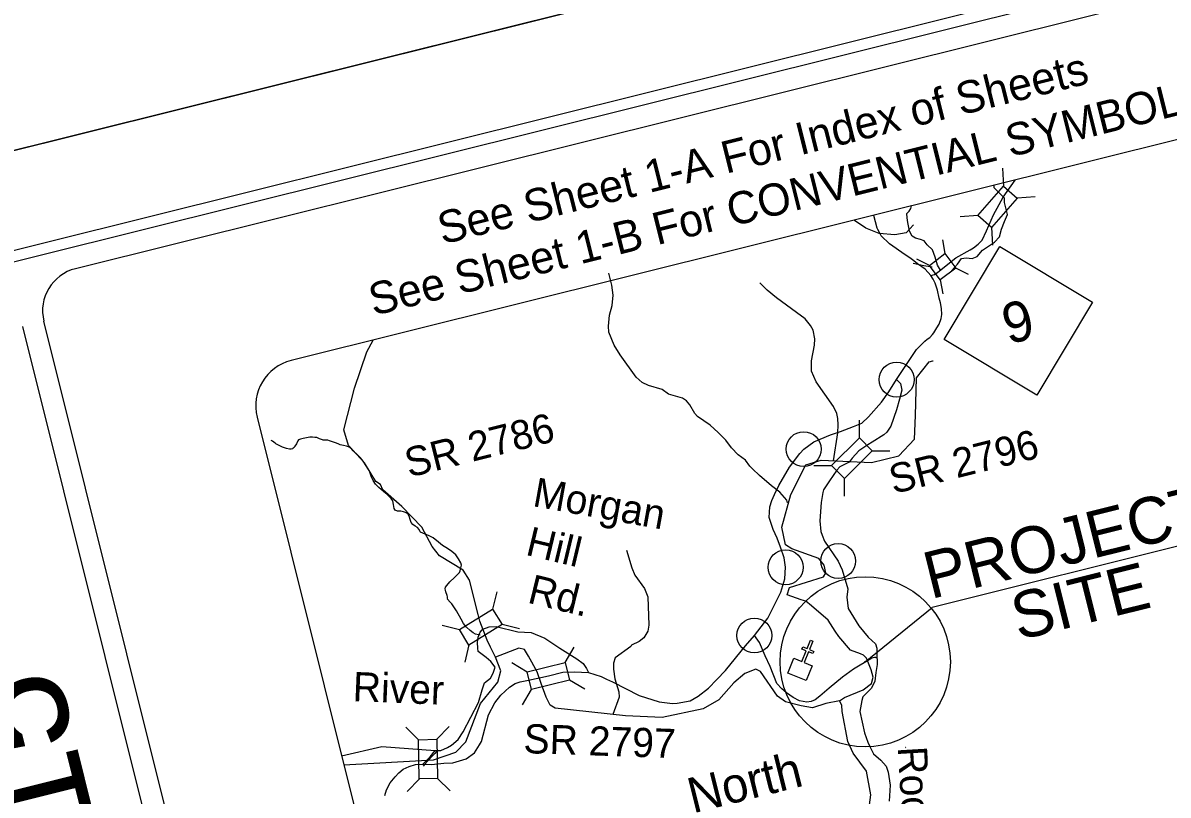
# Model space of a CAD drawing. Extents: x 1030323 to 1034123, y 654802 to 657751.
# Drawn here: x 1030543.2 to 1030807.6, y 656841.8 to 657020.2 of the extents above; entities that cross this region are included whole.
import ezdxf

# ---------------------------------------------------------------- set-up
doc = ezdxf.new("R2010")
doc.units = 0
for name, color, linetype in [('COGO Default Parcel', 7, 'Continuous'), ('Default', 7, 'Continuous'), ('Old_Level_1', 7, 'Continuous'), ('Prop Dimension', 7, 'Continuous'), ('Prop Dimension Text', 7, 'Continuous'), ('Prop Horizontal Alignment', 7, 'Continuous'), ('Prop Horizontal Alignment Tick Large', 7, 'Continuous'), ('Prop RDY Alternate Text Blue', 7, 'Continuous'), ('Prop Shade Light', 7, 'Continuous'), ('Prop Shade Medium', 7, 'Continuous'), ('Sheet Cutting Line CELL', 7, 'Continuous'), ('Sheet Plot Border Inside CELL', 7, 'Continuous'), ('Sheet Plot Border Outside CELL', 7, 'Continuous'), ('Sheet Title CELL', 7, 'Continuous')]:
    doc.layers.add(name, color=color, linetype=linetype)

msp = doc.modelspace()

# ---------------------------------------------------------------- linework, layer by layer
at = {"layer": 'COGO Default Parcel'}
for points in [[(1030757.59, 656962.93), (1030758.96, 656964.51), (1030759.89, 656965.76), (1030760.97, 656965.96), (1030762.35, 656965.82), (1030763.5, 656966.28), (1030764.76, 656967.71), (1030767.57, 656969.56), (1030768.71, 656970.77), (1030769.18, 656972.59), (1030769.87, 656974.36), (1030770.57, 656975.92), (1030769.87, 656978.74), (1030769.83, 656979.75), (1030767.45, 656982.14), (1030767.43, 656982.67)], [(1030740.61, 656972.5), (1030740.45, 656972.82), (1030739.66, 656975.74)], [(1030755.09, 656963.07), (1030754.36, 656964.22), (1030753.84, 656966.08), (1030753.21, 656967.75), (1030752.02, 656968.91), (1030751.32, 656969.9), (1030750.47, 656970.14), (1030749.29, 656970.51), (1030748.54, 656970.96), (1030747.93, 656972.11), (1030747.73, 656972.93), (1030747.54, 656974.1), (1030747.37, 656975.2), (1030747.27, 656976.15), (1030747.8, 656976.68), (1030748.24, 656977.35), (1030748.38, 656977.92)], [(1030748.82, 656973.55), (1030747.18, 656971.69), (1030744.55, 656971.25), (1030740.9, 656971.56), (1030737.85, 656972.8), (1030735.45, 656974.44), (1030735.07, 656974.6)], [(1030752.84, 656961.88), (1030751.5, 656963.33), (1030749.76, 656964.55), (1030748.91, 656965.24), (1030747.97, 656965.92), (1030746.94, 656966.65), (1030743.29, 656969.16), (1030741.38, 656971.05), (1030740.96, 656971.81), (1030740.61, 656972.5)], [(1030719.77, 656909.34), (1030719.6, 656909.97), (1030718.01, 656911.83), (1030716.02, 656913.3), (1030713.28, 656915.69), (1030711.63, 656917.16), (1030711.04, 656917.81), (1030710.08, 656919.17), (1030708.35, 656920.47), (1030706.81, 656922.08), (1030705.54, 656923.82), (1030703.75, 656925.59), (1030701.9, 656927.28), (1030698.93, 656929.32), (1030698.38, 656929.99), (1030697.17, 656932), (1030696.46, 656932.89), (1030695.47, 656933.49), (1030692.25, 656934.44), (1030690.8, 656935.51), (1030687.65, 656936.47), (1030686.16, 656937.16), (1030684.82, 656938.4), (1030681.08, 656943.51), (1030679.71, 656945.75), (1030678.47, 656948.76), (1030678.4, 656950.12), (1030678.63, 656952.7), (1030679.23, 656954.91), (1030679.51, 656957.28), (1030679.19, 656959.63), (1030678.53, 656962.36)], [(1030730.35, 656919.08), (1030731.39, 656925.48), (1030731.44, 656927.35), (1030731.34, 656928.86), (1030731.1, 656929.96), (1030730.38, 656931.59), (1030726.4, 656937.29), (1030725.32, 656939.74), (1030725.25, 656942.14), (1030725.99, 656945.8), (1030726.03, 656947.19), (1030725.68, 656949.19), (1030725.07, 656950.29), (1030723.81, 656951.85), (1030721.85, 656953.33), (1030717.22, 656956.69), (1030715.06, 656958.46), (1030713.35, 656960.17)], [(1030744.94, 656937.8), (1030749.56, 656944.78), (1030751.49, 656946.65), (1030752.03, 656947.18), (1030752.64, 656947.52), (1030753.23, 656948.19), (1030753.53, 656948.64), (1030754.26, 656949.73), (1030754.76, 656950.58), (1030755.24, 656951.94), (1030755.37, 656952.84), (1030755.29, 656954.27), (1030755.04, 656955.53), (1030754.79, 656956.63), (1030754.34, 656958.45), (1030753.85, 656960.12), (1030753.38, 656961), (1030752.84, 656961.88)], [(1030652.3, 656873.67), (1030651.19, 656876.02), (1030650.44, 656877.61), (1030648.69, 656881.99), (1030648.32, 656883.54), (1030646.31, 656891.47), (1030644.87, 656893.83), (1030639.37, 656897.11), (1030637.67, 656899.23), (1030635.31, 656903.71), (1030630.72, 656908.48), (1030626.34, 656912.32), (1030625.75, 656913.6), (1030624.68, 656914.27), (1030622.05, 656918.57), (1030618.4, 656922.57), (1030617.32, 656926.18), (1030619.74, 656935.86), (1030622.6, 656944.23), (1030624.09, 656946.93)], [(1030723.94, 656886.61), (1030722.92, 656886.92), (1030719.67, 656888.08), (1030720.23, 656889.82), (1030728.02, 656892.23), (1030728.6, 656893.16), (1030728.22, 656894.91), (1030726.95, 656896.52), (1030720.74, 656898.71), (1030719.3, 656899.67), (1030718.43, 656903.7), (1030720.53, 656911.28), (1030723.96, 656918.14), (1030727.54, 656919.22), (1030739.15, 656918.63), (1030745.42, 656920.2), (1030749.07, 656924.02), (1030749.29, 656929.53), (1030749.5, 656938.22), (1030752.42, 656941.95), (1030753.31, 656942.15)], [(1030753.31, 656942.15), (1030753.39, 656942.18)], [(1030712.1, 656878.7), (1030715.17, 656882.68), (1030718.19, 656888.73), (1030719.13, 656891.77), (1030719.31, 656894.46), (1030718.99, 656896.62), (1030718.15, 656899.12), (1030717.35, 656901.21), (1030716.46, 656903.2), (1030715.52, 656905.96), (1030715.68, 656908.41), (1030716.11, 656909.91), (1030716.75, 656911.3), (1030717.71, 656913.36), (1030720.18, 656917.56), (1030722.61, 656920.77), (1030723.48, 656921.75), (1030725.86, 656923.42), (1030729.66, 656925.08), (1030732, 656925.85), (1030734.99, 656926.96), (1030736.94, 656927.78), (1030738.43, 656929.18), (1030741.47, 656932.58), (1030743.15, 656934.97), (1030744.94, 656937.8)], [(1030744.94, 656937.8), (1030745.87, 656936.89), (1030746.11, 656935.4), (1030745.58, 656933.29), (1030744.89, 656930.81), (1030743.57, 656927.09), (1030742.71, 656925.69), (1030742, 656925.02), (1030739.33, 656923.32), (1030738.33, 656922.75), (1030736.2, 656921.34), (1030734.68, 656919.66)], [(1030734.68, 656919.66), (1030733.95, 656918.76), (1030731.86, 656917.66), (1030731.14, 656916.87), (1030729.46, 656914.42), (1030728.09, 656912.38), (1030727.87, 656911.74), (1030727.52, 656909.39), (1030727.19, 656905.19), (1030727.47, 656902.71), (1030727.78, 656901.84), (1030728.27, 656900.49), (1030731.44, 656895.9), (1030732.36, 656893.89), (1030733.71, 656889.46), (1030733.44, 656887.58), (1030733.73, 656884.92), (1030736.19, 656880.9), (1030738.36, 656878.29), (1030740.09, 656876.76), (1030740.38, 656875.78), (1030740.37, 656874.73)], [(1030682.55, 656898.42), (1030683.81, 656894.3), (1030684.49, 656892.66), (1030686.76, 656889.54), (1030687.51, 656887.61), (1030687.76, 656881.08), (1030687.52, 656879.73), (1030686.55, 656878.18), (1030685.51, 656877.32), (1030683.75, 656876.5), (1030683.6, 656876.17), (1030679.98, 656873.57), (1030679.59, 656872.29), (1030679.55, 656870.91), (1030679.91, 656868.72), (1030680.78, 656865.67), (1030680.85, 656864.49), (1030679.44, 656860.45)], [(1030731.57, 656878.5), (1030730.77, 656879.71), (1030729.12, 656882.21), (1030725.29, 656885.53), (1030723.94, 656886.61)], [(1030673.82, 656870.18), (1030676.71, 656869.21), (1030677.93, 656868.65), (1030679.33, 656867.98), (1030685.48, 656864.84), (1030690.09, 656863.36), (1030693.2, 656863.03), (1030694.27, 656863.08), (1030697.26, 656863.63), (1030699.13, 656864.66), (1030701.49, 656866.57), (1030703.46, 656868.54), (1030705.44, 656870.6), (1030710.05, 656876.34), (1030712.1, 656878.7)], [(1030731.76, 656863.61), (1030732.92, 656864.35), (1030737.18, 656866.15), (1030739.15, 656867.63), (1030739.53, 656869.06), (1030739.08, 656870.77), (1030738, 656873.43), (1030737.31, 656874.18), (1030736.58, 656874.43), (1030734.26, 656875.3), (1030731.57, 656878.5)], [(1030731.76, 656863.61), (1030728.56, 656862.97), (1030725.53, 656862.03), (1030722.92, 656862.47), (1030719.32, 656863.36), (1030717.47, 656864.72), (1030713.48, 656870.36), (1030712.43, 656870.92), (1030709.86, 656869.9), (1030707.36, 656867.8), (1030703.87, 656863.82), (1030700.28, 656861.78), (1030690.79, 656859.73), (1030682.33, 656860.13), (1030666.13, 656861.94), (1030664.97, 656862.63), (1030664, 656864.49), (1030662.86, 656867.61), (1030661.97, 656870.29), (1030659.98, 656873.93), (1030659.04, 656875.45), (1030657.74, 656875.77), (1030652.3, 656873.67)], [(1030617.31, 656848.84), (1030637.98, 656850.01), (1030643.19, 656851.75), (1030645.47, 656854.11), (1030648.84, 656863.02), (1030652.9, 656867.93), (1030653.59, 656870.53), (1030652.3, 656873.67)], [(1030740.37, 656874.73), (1030740.48, 656872.03), (1030740.15, 656870.12), (1030739.9, 656868.12), (1030739.12, 656866.54), (1030737.17, 656864.5), (1030736.88, 656863.68), (1030736.46, 656861.15), (1030737.55, 656856.22), (1030738.32, 656854.05), (1030738.84, 656852.92), (1030739.62, 656851.38), (1030741.32, 656849.87), (1030742.53, 656848.49), (1030742.98, 656847.12), (1030743.47, 656844.15), (1030743.19, 656840.4)], [(1030664.59, 656869.42), (1030667.88, 656870.21), (1030670.57, 656870.32), (1030673.82, 656870.18)], [(1030635.53, 656849.01), (1030637.56, 656848.91), (1030640.42, 656849.19), (1030642.45, 656849.32), (1030645.57, 656850.2), (1030647.51, 656851.57), (1030648.65, 656853.45), (1030649.12, 656854.23), (1030650.74, 656860.39), (1030652.19, 656863.18), (1030653.52, 656864.9), (1030655.58, 656866.77), (1030656.89, 656867.59), (1030658.02, 656867.99), (1030659.97, 656868.36), (1030664.59, 656869.42)], [(1030763.46, 656805.71), (1030761.88, 656806.58), (1030753.15, 656807.52), (1030746.75, 656809.86), (1030743.2, 656811.93), (1030742.76, 656816.18), (1030741.52, 656818.34), (1030739.98, 656819.77), (1030739.15, 656822.21), (1030739.79, 656827.13), (1030738.2, 656832.4), (1030738.18, 656836.13), (1030738.96, 656841.88), (1030737.95, 656847.35), (1030734.88, 656851.54), (1030733.68, 656854.21), (1030732.33, 656861.16), (1030732.26, 656862.62), (1030731.76, 656863.61)], [(1030626.78, 656841.76), (1030627.15, 656843.07), (1030628.02, 656844.66), (1030629.18, 656846.06), (1030629.98, 656846.99), (1030630.99, 656847.79), (1030632.38, 656848.43), (1030633.84, 656848.91), (1030635.53, 656849.01)]]:
    msp.add_lwpolyline(points, dxfattribs=at)
msp.add_circle((1030737.7, 656872.62), 19.65, dxfattribs=at)
at = {"layer": 'Default'}
for p, q in [((1030755.88, 656947.11), (1030768.75, 656968.53)), ((1030768.75, 656968.53), (1030790.17, 656955.66)), ((1030790.17, 656955.66), (1030777.3, 656934.24)), ((1030777.3, 656934.24), (1030755.88, 656947.11)), ((1030668.39, 656872.48), (1030670.51, 656876.01)), ((1030723.05, 656875.58), (1030723.27, 656876.1)), ((1030724.08, 656875.16), (1030723.05, 656875.58)), ((1030723.07, 656872.71), (1030724.08, 656875.16)), ((1030723.27, 656876.1), (1030724.3, 656875.67)), ((1030724.3, 656875.67), (1030725.09, 656877.61)), ((1030725.61, 656877.4), (1030724.81, 656875.46)), ((1030724.81, 656875.46), (1030725.84, 656875.04)), ((1030725.09, 656877.61), (1030725.61, 656877.4)), ((1030656.1, 656872.44), (1030659.63, 656870.32)), ((1030719.83, 656870.03), (1030721.24, 656873.46)), ((1030721.24, 656873.46), (1030723.07, 656872.71)), ((1030724.6, 656874.95), (1030723.59, 656872.5)), ((1030723.59, 656872.5), (1030725.44, 656871.73)), ((1030725.63, 656874.52), (1030724.6, 656874.95)), ((1030725.84, 656875.04), (1030725.63, 656874.52)), ((1030724.03, 656868.3), (1030719.83, 656870.03)), ((1030725.44, 656871.73), (1030724.03, 656868.3)), ((1030669.39, 656868.49), (1030672.92, 656866.37)), ((1030658.53, 656862.7), (1030660.65, 656866.23))]:
    msp.add_line(p, q, dxfattribs=at)
for points in [[(1030769.55, 656979.93), (1030772.31, 656983.88)], [(1030754.46, 656962.61), (1030758.59, 656965.93), (1030761.94, 656967.75), (1030762.71, 656968.28), (1030763.79, 656969.1), (1030764.66, 656970.05), (1030765.69, 656972.14), (1030767.32, 656975.89), (1030768.59, 656978.27), (1030769.55, 656979.93)], [(1030753.14, 656963.76), (1030751.21, 656964.09), (1030748.76, 656964.61)], [(1030752.84, 656961.88), (1030753.72, 656962.12), (1030754.46, 656962.61)], [(1030648.78, 656878.77), (1030648.42, 656878.83), (1030647.71, 656879.04), (1030647.15, 656879.33), (1030646.5, 656879.86), (1030645.62, 656880.61), (1030644.9, 656881.47), (1030644.37, 656882.51), (1030643.34, 656884.4), (1030642.21, 656885.98), (1030641.9, 656886.33), (1030641.2, 656887.19), (1030641.21, 656887.25), (1030641.26, 656887.61), (1030641.18, 656887.96), (1030640.89, 656888.75), (1030640.76, 656889.17), (1030640.71, 656889.47), (1030640.76, 656889.83), (1030641.1, 656890.23), (1030641.82, 656891.1), (1030642.84, 656892.1), (1030643.69, 656892.91), (1030643.98, 656893.27), (1030644.14, 656893.63), (1030644.29, 656894.32), (1030644.46, 656894.91), (1030644.29, 656895.47), (1030643.79, 656896.43), (1030643.14, 656897.3), (1030642.25, 656898.11), (1030641.25, 656898.8), (1030640.08, 656899.49), (1030639.17, 656900.26), (1030637.95, 656901.25), (1030637.02, 656901.76), (1030635.01, 656902.54), (1030634.99, 656902.59), (1030634.97, 656902.64), (1030634.69, 656903.17), (1030634.31, 656903.62), (1030633.8, 656903.98), (1030633.26, 656904.33), (1030632.84, 656904.78), (1030632.63, 656905.52), (1030632.41, 656906.26), (1030632.05, 656906.82), (1030631.53, 656907.15), (1030631.08, 656907.3), (1030630.44, 656907.4), (1030629.68, 656907.44), (1030629.15, 656907.67), (1030628.91, 656908.06), (1030628.8, 656908.99), (1030628.62, 656909.78), (1030628.23, 656910.38), (1030627.35, 656911.25), (1030626.47, 656911.96), (1030625.41, 656912.85), (1030624.62, 656913.62), (1030624.08, 656914.49), (1030623.72, 656915.3), (1030623.28, 656916.4), (1030623, 656917.04), (1030622.5, 656917.92), (1030621.8, 656918.97), (1030621.13, 656919.77), (1030620.33, 656920.56), (1030619.5, 656921.38), (1030619.14, 656921.72), (1030618.7, 656922.13), (1030618.55, 656922.17), (1030618.36, 656922.3), (1030617.91, 656922.4), (1030617.21, 656922.61), (1030616.5, 656922.75), (1030615.97, 656922.95), (1030615.36, 656923.22), (1030614.7, 656923.44), (1030614.01, 656923.7), (1030613.6, 656923.8), (1030613.19, 656923.85), (1030612.82, 656923.83), (1030612.52, 656923.84), (1030612.36, 656923.88), (1030611.67, 656924.16), (1030611.11, 656924.4), (1030610.65, 656924.46), (1030610.09, 656924.53), (1030609.48, 656924.49), (1030607.92, 656924.2), (1030607.32, 656924.08), (1030607.04, 656924.01), (1030606.84, 656923.91), (1030606.69, 656923.68), (1030606.36, 656923.01), (1030606.02, 656922.43), (1030605.82, 656922.15), (1030605.64, 656921.98), (1030605.45, 656921.85), (1030605.18, 656921.75), (1030604.77, 656921.73), (1030604.07, 656921.86), (1030603.13, 656922.2), (1030602.2, 656922.63), (1030601.61, 656922.96), (1030601.44, 656923.13), (1030601.15, 656923.37), (1030600.81, 656923.59), (1030600.5, 656923.74)], [(1030649.26, 656879.99), (1030649.43, 656880.18), (1030650.88, 656880.74), (1030652.51, 656880.8), (1030657.46, 656879.51), (1030660.59, 656879.4), (1030663.69, 656878.11), (1030667.21, 656875.79), (1030671.13, 656873.28), (1030672.54, 656872.21), (1030673.36, 656871.08), (1030673.82, 656870.18)], [(1030638.4, 656852.16), (1030639.7, 656852.17), (1030641.28, 656852.8), (1030642.15, 656853.4), (1030643.74, 656854.68), (1030644.88, 656856.42), (1030648.37, 656863.24), (1030649.22, 656866.14), (1030649.76, 656867.8), (1030651.14, 656868.87), (1030651.78, 656869.99), (1030652.24, 656871.37), (1030651.25, 656872.73), (1030650.19, 656873.61), (1030648.35, 656874.99), (1030648.22, 656875.8), (1030648.17, 656877.09), (1030648.33, 656878.28), (1030648.81, 656879.47), (1030649.26, 656879.99)], [(1030738.95, 656873.33), (1030735, 656870.93), (1030732.42, 656869.04), (1030729.36, 656866.56), (1030727.22, 656864.66), (1030726.13, 656863.83), (1030725.18, 656863.44), (1030724.17, 656863.3), (1030722.48, 656863.61), (1030721.06, 656864.38), (1030719.55, 656865.44), (1030718.46, 656866.4), (1030717.26, 656867.63), (1030715.77, 656871.53), (1030714.61, 656874.03), (1030713.29, 656877.05), (1030712.1, 656878.7)], [(1030616.79, 656850.92), (1030626.12, 656853.03), (1030638.4, 656852.16)], [(1030638.72, 656851.94), (1030638.32, 656851.44), (1030637.95, 656851.09), (1030636.66, 656849.71), (1030636.03, 656848.95), (1030635.65, 656848.55)], [(1030636.71, 656850.12), (1030637.27, 656850.66), (1030638.4, 656852.16)], [(1030635.53, 656849.01), (1030636.71, 656850.12)]]:
    msp.add_lwpolyline(points, dxfattribs=at)
msp.add_lwpolyline([(1030659.63, 656870.32), (1030668.39, 656872.5), (1030669.4, 656868.42), (1030660.65, 656866.23)], close=True, dxfattribs=at)
at = {"layer": 'Old_Level_1'}
for p, q in [((1030747.06, 656852.81), (1030747, 656852.8)), ((1030747.02, 656852.84), (1030747.03, 656852.78))]:
    msp.add_line(p, q, dxfattribs=at)
at = {"layer": 'Prop Dimension'}
for p in [(1030817.25, 656901.17), (1030737.7, 656872.62)]:
    msp.add_line(p, (1030753.13, 656885.18), dxfattribs=at)
at = {"layer": 'Prop Horizontal Alignment'}
msp.add_line((1030740.14, 656873.64), (1030740.42, 656873.63), dxfattribs=at)
msp.add_arc((1030740.12, 656871.27), 2.37, 89.4693, 119.5824, dxfattribs=at)
at = {"layer": 'Prop Horizontal Alignment Tick Large'}
msp.add_line((1030737.7, 656872.62), (1030737.63, 656872.74), dxfattribs=at)
msp.add_line((1030737.7, 656872.62), (1030737.63, 656872.74), dxfattribs=at)
at = {"layer": 'Prop RDY Alternate Text Blue'}
msp.add_line((1030740.57, 656873.33), (1030740.57, 656873.33), dxfattribs=at)
at = {"layer": 'Prop Shade Light'}
for p, q in [((1030769.35, 656986.62), (1030769.62, 656982.51)), ((1030776.89, 656980), (1030772.78, 656979.73)), ((1030763.72, 656975.68), (1030759.61, 656975.41)), ((1030766.82, 656972.97), (1030767.09, 656968.86)), ((1030755.52, 656970.11), (1030756.1, 656966.9)), ((1030752.54, 656964.13), (1030749.63, 656965.59)), ((1030761.53, 656962.07), (1030758.62, 656963.52)), ((1030755.01, 656960.83), (1030755.59, 656957.62)), ((1030736.34, 656924.31), (1030736.35, 656928.43)), ((1030739.24, 656921.39), (1030743.36, 656921.38)), ((1030725.81, 656917.98), (1030729.93, 656917.97)), ((1030732.88, 656910.86), (1030732.9, 656914.98)), ((1030652.63, 656888.81), (1030651.67, 656884.81)), ((1030644.02, 656880.03), (1030640.01, 656880.99)), ((1030657.87, 656880.25), (1030653.87, 656881.21)), ((1030646.17, 656876.52), (1030645.21, 656872.52)), ((1030631.6, 656857.5), (1030634.56, 656854.64)), ((1030641.63, 656857.69), (1030638.77, 656854.72)), ((1030634.81, 656845.63), (1030631.95, 656842.66)), ((1030638.92, 656845.7), (1030641.89, 656842.85))]:
    msp.add_line(p, q, dxfattribs=at)
for points in [[(1030772.78, 656979.73), (1030766.83, 656972.95), (1030763.67, 656975.73), (1030769.62, 656982.51)], [(1030758.62, 656963.52), (1030755.02, 656960.82), (1030752.5, 656964.19), (1030756.1, 656966.9)], [(1030729.93, 656917.97), (1030736.33, 656924.33), (1030739.3, 656921.34), (1030732.9, 656914.98)], [(1030653.87, 656881.21), (1030646.18, 656876.5), (1030643.98, 656880.1), (1030651.67, 656884.81)], [(1030638.77, 656854.72), (1030638.94, 656845.7), (1030634.73, 656845.63), (1030634.56, 656854.64)]]:
    msp.add_lwpolyline(points, close=True, dxfattribs=at)
at = {"layer": 'Prop Shade Medium'}
for centre in [(1030744.94, 656937.8), (1030723.48, 656921.75), (1030731.44, 656895.9), (1030719.31, 656894.46), (1030712.1, 656878.7)]:
    msp.add_circle(centre, 4.03, dxfattribs=at)
at = {"layer": 'Sheet Cutting Line CELL'}
msp.add_line((1030322.99, 656936.36), (1031956.96, 657343.76), dxfattribs=at)
at = {"layer": 'Sheet Plot Border Inside CELL'}
msp.add_lwpolyline([(1030596.28, 655893.96), (1032213.28, 656297.13), (1031958.03, 657320.89), (1030341.03, 656917.72)], close=True, dxfattribs=at)
at = {"layer": 'Sheet Plot Border Outside CELL'}
msp.add_lwpolyline([(1031956.96, 657343.76), (1030322.99, 656936.36), (1030589.1, 655869.05), (1032223.08, 656276.44)], close=True, dxfattribs=at)
at = {"layer": 'Sheet Title CELL'}
for p, q in [((1030843.2, 657001.56), (1030605.16, 656942.21)), ((1030789.97, 655960.36), (1030543.21, 656950.06)), ((1030750.07, 656141.07), (1030548.07, 656951.27)), ((1030597.29, 656929.11), (1030657.8, 656686.44))]:
    msp.add_line(p, q, dxfattribs=at)
for points in [[(1031936.83, 657312.97), (1030500.76, 656954.93)], [(1031933.17, 657306.91), (1030555.36, 656963.38)]]:
    msp.add_lwpolyline(points, dxfattribs=at)
for centre, radius in [((1030557.76, 656953.73), 10), ((1030607.77, 656931.73), 10.8)]:
    msp.add_arc(centre, radius, 104, 194, dxfattribs=at)

# ---------------------------------------------------------------- texts
at = {"layer": 'Default'}
for s, height, rotation, p in [('9', 9.28, 14, (1030770.68, 656945.9)), ('SR 2786', 6.75, 14, (1030632.36, 656915.17)), ('SR 2796', 6.75, 14, (1030744.19, 656911.36)), ('Morgan', 6.75, 349.7745, (1030660.68, 656908.61)), ('Hill', 6.75, 346.5003, (1030659.03, 656897.38)), ('Rd.', 6.75, 346.2578, (1030659.47, 656886.33)), ('River', 6.75, 357.631, (1030619.26, 656863.56)), ('SR 2797', 6.75, 358.0466, (1030658.71, 656851.55)), ('North', 8.149, 14, (1030697.9, 656837.59)), ('Rock', 6.75, 273.3646, (1030745.19, 656852.91))]:
    msp.add_text(s, height=height, rotation=rotation, dxfattribs=at).set_placement(p)
at = {"layer": 'Prop Dimension Text'}
for s, p in [('PROJECT ', (1030752.81, 656887.08)), ('SITE', (1030773.05, 656877.54))]:
    msp.add_text(s, height=10.8, rotation=14, dxfattribs=at).set_placement(p)
at = {"layer": 'Sheet Title CELL'}
for s, height, rotation, p in [('See Sheet 1-A For Index of Sheets', 7.4395, 14, (1030640.05, 656969)), ('See Sheet 1-B For CONVENTIAL SYMBOLS', 7.4395, 14, (1030624.15, 656952.52)), ('  B-4715', 25, 104, (1030581.51, 656749.41))]:
    msp.add_text(s, height=height, rotation=rotation, dxfattribs=at).set_placement(p)

doc.saveas('drawing.dxf')
